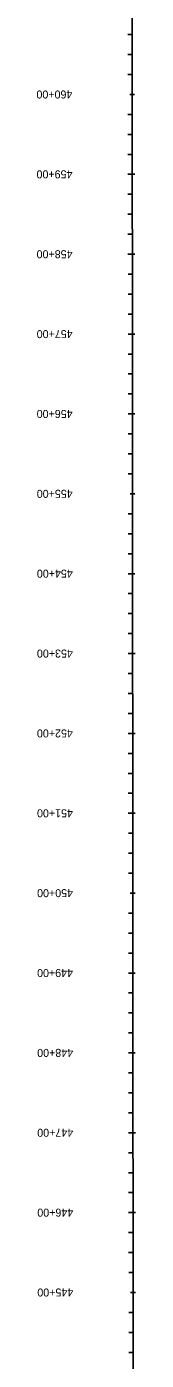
# Model space of a CAD drawing. Extents: x 23417911 to 23421158, y 6737892 to 6791804.
# Drawn here: x 23420710 to 23420835, y 6769913 to 6771582 of the extents above; entities that cross this region are included whole.
import ezdxf

# ---------------------------------------------------------------- set-up
doc = ezdxf.new("R2010")
doc.units = 0
for name, color, linetype in [('Alignment', 7, 'Continuous'), ('TextAlignmentLrg', 7, 'Continuous'), ('TextAlignmentSml', 7, 'Continuous')]:
    doc.layers.add(name, color=color, linetype=linetype)

msp = doc.modelspace()

# ---------------------------------------------------------------- linework, layer by layer
at = {"layer": 'Alignment'}
msp.add_line((23420834.6, 6764732), (23420829.5, 6771769.1), dxfattribs=at)
msp.add_line((23420834.6, 6764732), (23420829.5, 6771769.1), dxfattribs=at)
at = {"layer": 'TextAlignmentLrg'}
for p, q in [((23420826.6, 6771497.6), (23420832.7, 6771497.6)), ((23420829.7, 6771397.6), (23420824.3, 6771397.6)), ((23420829.8, 6771297.6), (23420824.3, 6771297.6)), ((23420829.9, 6771197.6), (23420824.4, 6771197.6)), ((23420829.9, 6771097.6), (23420824.5, 6771097.6)), ((23420827, 6770997.6), (23420833.1, 6770997.6)), ((23420830.1, 6770897.6), (23420824.6, 6770897.6)), ((23420830.2, 6770797.6), (23420824.7, 6770797.6)), ((23420830.2, 6770697.6), (23420824.8, 6770697.6)), ((23420830.3, 6770597.6), (23420824.8, 6770597.6)), ((23420827.3, 6770497.6), (23420833.4, 6770497.6)), ((23420830.5, 6770397.6), (23420825, 6770397.6)), ((23420830.5, 6770297.6), (23420825.1, 6770297.6)), ((23420830.6, 6770197.6), (23420825.1, 6770197.6)), ((23420830.7, 6770097.6), (23420825.2, 6770097.6)), ((23420827.7, 6769997.6), (23420833.8, 6769997.6))]:
    msp.add_line(p, q, dxfattribs=at)
at = {"layer": 'TextAlignmentSml'}
for p, q in [((23420829.6, 6771572.6), (23420824.1, 6771572.6)), ((23420829.6, 6771547.6), (23420824.2, 6771547.6)), ((23420829.6, 6771522.6), (23420824.2, 6771522.6)), ((23420826.6, 6771497.6), (23420832.7, 6771497.6)), ((23420829.7, 6771472.6), (23420824.2, 6771472.6)), ((23420829.7, 6771447.6), (23420824.2, 6771447.6)), ((23420829.7, 6771422.6), (23420824.2, 6771422.6)), ((23420826.7, 6771397.6), (23420832.8, 6771397.6)), ((23420829.7, 6771372.6), (23420824.3, 6771372.6)), ((23420829.8, 6771347.6), (23420824.3, 6771347.6)), ((23420829.8, 6771322.6), (23420824.3, 6771322.6)), ((23420826.7, 6771297.6), (23420832.9, 6771297.6)), ((23420829.8, 6771272.6), (23420824.4, 6771272.6)), ((23420829.8, 6771247.6), (23420824.4, 6771247.6)), ((23420829.9, 6771222.6), (23420824.4, 6771222.6)), ((23420826.8, 6771197.6), (23420832.9, 6771197.6)), ((23420829.9, 6771172.6), (23420824.4, 6771172.6)), ((23420829.9, 6771147.6), (23420824.4, 6771147.6)), ((23420829.9, 6771122.6), (23420824.5, 6771122.6)), ((23420826.9, 6771097.6), (23420833, 6771097.6)), ((23420830, 6771072.6), (23420824.5, 6771072.6)), ((23420830, 6771047.6), (23420824.5, 6771047.6)), ((23420830, 6771022.6), (23420824.5, 6771022.6)), ((23420827, 6770997.6), (23420833.1, 6770997.6)), ((23420830, 6770972.6), (23420824.6, 6770972.6)), ((23420830.1, 6770947.6), (23420824.6, 6770947.6)), ((23420830.1, 6770922.6), (23420824.6, 6770922.6)), ((23420827, 6770897.6), (23420833.1, 6770897.6)), ((23420830.1, 6770872.6), (23420824.6, 6770872.6)), ((23420830.1, 6770847.6), (23420824.7, 6770847.6)), ((23420830.1, 6770822.6), (23420824.7, 6770822.6)), ((23420827.1, 6770797.6), (23420833.2, 6770797.6)), ((23420830.2, 6770772.6), (23420824.7, 6770772.6)), ((23420830.2, 6770747.6), (23420824.7, 6770747.6)), ((23420830.2, 6770722.6), (23420824.8, 6770722.6)), ((23420827.2, 6770697.6), (23420833.3, 6770697.6)), ((23420830.3, 6770672.6), (23420824.8, 6770672.6)), ((23420830.3, 6770647.6), (23420824.8, 6770647.6)), ((23420830.3, 6770622.6), (23420824.8, 6770622.6)), ((23420827.2, 6770597.6), (23420833.4, 6770597.6)), ((23420830.3, 6770572.6), (23420824.9, 6770572.6)), ((23420830.3, 6770547.6), (23420824.9, 6770547.6)), ((23420830.4, 6770522.6), (23420824.9, 6770522.6)), ((23420827.3, 6770497.6), (23420833.4, 6770497.6)), ((23420830.4, 6770472.6), (23420824.9, 6770472.6)), ((23420830.4, 6770447.6), (23420825, 6770447.6)), ((23420830.4, 6770422.6), (23420825, 6770422.6)), ((23420827.4, 6770397.6), (23420833.5, 6770397.6)), ((23420830.5, 6770372.6), (23420825, 6770372.6)), ((23420830.5, 6770347.6), (23420825, 6770347.6)), ((23420830.5, 6770322.6), (23420825, 6770322.6)), ((23420827.5, 6770297.6), (23420833.6, 6770297.6)), ((23420830.5, 6770272.6), (23420825.1, 6770272.6)), ((23420830.6, 6770247.6), (23420825.1, 6770247.6)), ((23420830.6, 6770222.6), (23420825.1, 6770222.6)), ((23420827.5, 6770197.6), (23420833.7, 6770197.6)), ((23420830.6, 6770172.6), (23420825.2, 6770172.6)), ((23420830.6, 6770147.6), (23420825.2, 6770147.6)), ((23420830.6, 6770122.6), (23420825.2, 6770122.6)), ((23420827.6, 6770097.6), (23420833.7, 6770097.6)), ((23420830.7, 6770072.6), (23420825.2, 6770072.6)), ((23420830.7, 6770047.6), (23420825.2, 6770047.6)), ((23420830.7, 6770022.6), (23420825.3, 6770022.6)), ((23420827.7, 6769997.6), (23420833.8, 6769997.6)), ((23420830.8, 6769972.6), (23420825.3, 6769972.6)), ((23420830.8, 6769947.6), (23420825.3, 6769947.6)), ((23420830.8, 6769922.6), (23420825.3, 6769922.6))]:
    msp.add_line(p, q, dxfattribs=at)

# ---------------------------------------------------------------- texts
at = {"layer": 'TextAlignmentLrg'}
for s, p in [('460+00', (23420754.6, 6771502.6)), ('455+00', (23420755, 6771002.6)), ('450+00', (23420755.4, 6770502.6)), ('445+00', (23420755.7, 6770002.6))]:
    msp.add_text(s, height=10.02, rotation=180.0416, dxfattribs=at).set_placement(p)
at = {"layer": 'TextAlignmentSml'}
for s, p in [('460+00', (23420754.6, 6771502.6)), ('459+00', (23420754.7, 6771402.6)), ('458+00', (23420754.8, 6771302.6)), ('457+00', (23420754.9, 6771202.6)), ('456+00', (23420754.9, 6771102.6)), ('455+00', (23420755, 6771002.6)), ('454+00', (23420755.1, 6770902.6)), ('453+00', (23420755.2, 6770802.6)), ('452+00', (23420755.2, 6770702.6)), ('451+00', (23420755.3, 6770602.6)), ('450+00', (23420755.4, 6770502.6)), ('449+00', (23420755.4, 6770402.6)), ('448+00', (23420755.5, 6770302.6)), ('447+00', (23420755.6, 6770202.6)), ('446+00', (23420755.7, 6770102.6)), ('445+00', (23420755.7, 6770002.6))]:
    msp.add_text(s, height=10.02, rotation=180.0416, dxfattribs=at).set_placement(p)

doc.saveas('drawing.dxf')
